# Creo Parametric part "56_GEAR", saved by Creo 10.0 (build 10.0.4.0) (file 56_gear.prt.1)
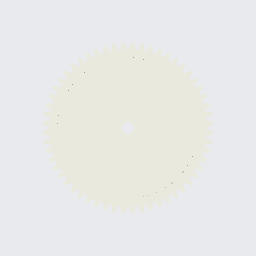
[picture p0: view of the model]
Units: millimeter Kilogram Sec (mmKs); MM, KILOGRAM, SECS

Created from: XX_SOLID_PART_MMKS_NEW_ABS.PRT

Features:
  1. datum plane "RIGHT"
  2. datum plane "TOP"
  3. datum plane "FRONT"
  4. coordinate system
  5. extrusion "Extrude 1"
  6. pattern "Pattern 1"
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
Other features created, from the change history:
  extruded cut "Extrude 2"
  extruded cut "Extrude 2 [2]"
  extruded cut "Extrude 2 [3]"
  extruded cut "Extrude 2 [4]"
  extruded cut "Extrude 2 [5]"
  extruded cut "Extrude 2 [6]"
  extruded cut "Extrude 2 [7]"
  extruded cut "Extrude 2 [8]"
  extruded cut "Extrude 2 [9]"
  extruded cut "Extrude 2 [10]"
  extruded cut "Extrude 2 [11]"
  extruded cut "Extrude 2 [12]"
  extrusion "Extrude 3"
  extruded cut "Extrude 4"
  pattern "Pattern 2"
  extruded cut "Extrude 4 [2]"
  extruded cut "Extrude 4 [3]"
  extruded cut "Extrude 4 [4]"
  extruded cut "Extrude 4 [5]"
  extruded cut "Extrude 4 [6]"
  extruded cut "Extrude 4 [7]"
  extruded cut "Extrude 4 [8]"
  extruded cut "Extrude 4 [9]"
  extruded cut "Extrude 4 [10]"
  extruded cut "Extrude 4 [11]"
  extruded cut "Extrude 4 [12]"
  extruded cut "Extrude 4 [13]"
  extruded cut "Extrude 4 [14]"
  extruded cut "Extrude 4 [15]"
  extruded cut "Extrude 4 [16]"
  extruded cut "Extrude 4 [17]"
  extruded cut "Extrude 4 [18]"
  extruded cut "Extrude 4 [19]"
  extruded cut "Extrude 4 [20]"
  extruded cut "Extrude 4 [21]"
  extruded cut "Extrude 4 [22]"
  extruded cut "Extrude 4 [23]"
  extruded cut "Extrude 4 [24]"
  extruded cut "Extrude 4 [25]"
  extruded cut "Extrude 4 [26]"
  extruded cut "Extrude 4 [27]"
  extruded cut "Extrude 4 [28]"
  extruded cut "Extrude 4 [29]"
  extruded cut "Extrude 4 [30]"
  extruded cut "Extrude 4 [31]"
  extruded cut "Extrude 4 [32]"
  extruded cut "Extrude 4 [33]"
  extruded cut "Extrude 4 [34]"
  extruded cut "Extrude 4 [35]"
  extruded cut "Extrude 4 [36]"
  extruded cut "Extrude 4 [37]"
  extruded cut "Extrude 4 [38]"
  extruded cut "Extrude 4 [39]"
  extruded cut "Extrude 4 [40]"
  extruded cut "Extrude 4 [41]"
  extruded cut "Extrude 4 [42]"
  extruded cut "Extrude 4 [43]"
  extruded cut "Extrude 4 [44]"
  extruded cut "Extrude 4 [45]"
  extruded cut "Extrude 4 [46]"
  extruded cut "Extrude 4 [47]"
  extruded cut "Extrude 4 [48]"
  extruded cut "Extrude 4 [49]"
  extruded cut "Extrude 4 [50]"
  extruded cut "Extrude 4 [51]"
  extruded cut "Extrude 4 [52]"
  extruded cut "Extrude 4 [53]"
  extruded cut "Extrude 4 [54]"
  extruded cut "Extrude 4 [55]"
  extruded cut "Extrude 4 [56]"
  extrusion "Extrude 5" (2 times)
  extruded cut "Extrude 6"
  extruded cut "Extrude 7"
  extruded cut "Extrude 8"

Surfaces: 142 plane, 72 cylinder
